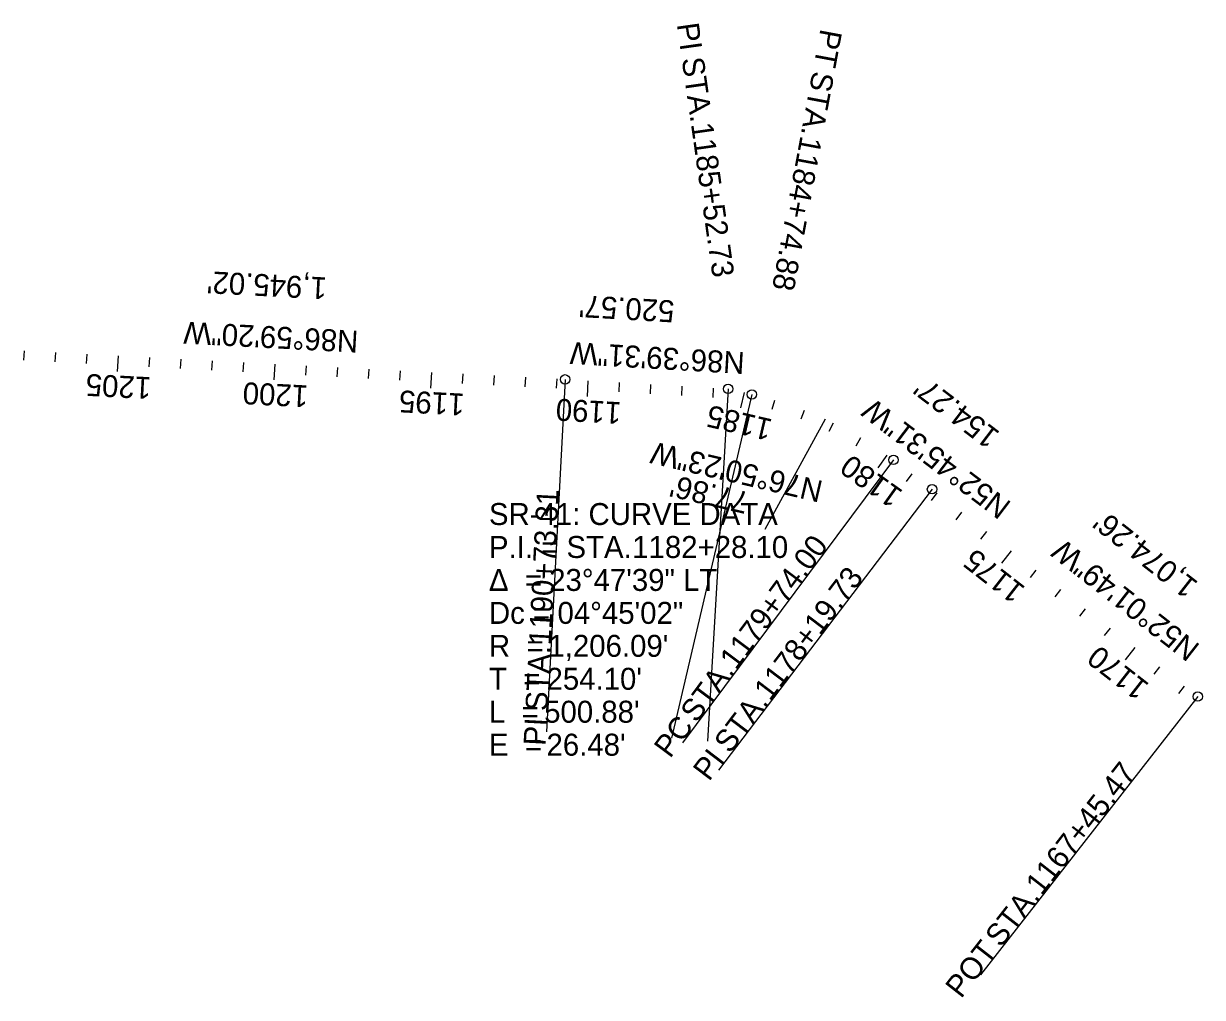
# Model space of a CAD drawing. Extents: x 99589 to 110840, y 526591 to 533644.
# Drawn here: x 107082 to 110840, y 526591 to 529695 of the extents above; entities that cross this region are included whole.
import ezdxf

# ---------------------------------------------------------------- set-up
doc = ezdxf.new("R2010")
doc.units = 0
for name, color, linetype in [('GE_P_Alignment_500_Bearings', 7, 'Continuous'), ('GE_P_Alignment_500_Cardinal_Points', 7, 'Continuous'), ('GE_P_Alignment_500_Curve_Data', 7, 'Continuous'), ('GE_P_Alignment_500_Distances', 7, 'Continuous'), ('GE_P_Alignment_500_Stations', 7, 'Continuous')]:
    doc.layers.add(name, color=color, linetype=linetype)

msp = doc.modelspace()

# ---------------------------------------------------------------- linework, layer by layer
at = {"layer": 'GE_P_Alignment_500_Cardinal_Points'}
for p, q in [((108808.4, 528561), (108749.3, 527437.6)), ((109328, 528530.7), (109262.5, 527407.6)), ((109403.9, 528513), (109147.7, 527417.5)), ((109855.3, 528304.4), (109183, 527402.3)), ((109978.1, 528211), (109297.3, 527315.4)), ((110825, 527550.1), (110132.8, 526663.2))]:
    msp.add_line(p, q, dxfattribs=at)
for centre in [(108808.4, 528561), (109328, 528530.7), (109403.9, 528513), (109855.3, 528304.4), (109978.1, 528211), (110825, 527550.1)]:
    msp.add_circle(centre, 15, dxfattribs=at)
at = {"layer": 'GE_P_Alignment_500_Curve_Data'}
msp.add_line((109637.1, 528433.7), (109445.2, 528082.6), dxfattribs=at)
at = {"layer": 'GE_P_Alignment_500_Stations'}
for p, q in [((107084, 528651.7), (107082.5, 528621.8)), ((107183.9, 528646.5), (107182.3, 528616.5)), ((107283.8, 528641.2), (107282.2, 528611.3)), ((107383.6, 528636), (107381, 528586)), ((107483.5, 528630.7), (107481.9, 528600.8)), ((107583.4, 528625.5), (107581.8, 528595.5)), ((107683.2, 528620.2), (107681.6, 528590.3)), ((107783.1, 528615), (107781.5, 528585)), ((107882.9, 528609.7), (107880.3, 528559.8)), ((107982.8, 528604.5), (107981.2, 528574.5)), ((108082.7, 528599.2), (108081.1, 528569.2)), ((108182.5, 528593.9), (108180.9, 528564)), ((108282.4, 528588.7), (108280.8, 528558.7)), ((108382.2, 528583.4), (108379.6, 528533.5)), ((108482.1, 528578.2), (108480.5, 528548.2)), ((108582, 528572.9), (108580.4, 528543)), ((108681.8, 528567.7), (108680.3, 528537.7)), ((108781.7, 528562.4), (108780.1, 528532.5)), ((108881.5, 528556.8), (108878.6, 528506.8)), ((108981.4, 528550.9), (108979.6, 528521)), ((109081.2, 528545.1), (109079.4, 528515.1)), ((109181, 528539.3), (109179.3, 528509.3)), ((109280.9, 528533.4), (109279.1, 528503.5)), ((109379.4, 528518.7), (109368, 528470)), ((109476.3, 528494), (109467.8, 528465.2)), ((109570.9, 528461.7), (109560, 528433.7)), ((109662.5, 528421.7), (109649.4, 528394.7)), ((109750.5, 528374.3), (109735.2, 528348.5)), ((109834.3, 528319.7), (109805.3, 528279)), ((109914.2, 528259.6), (109896, 528235.7)), ((109993.6, 528198.9), (109975.2, 528175.2)), ((110072.5, 528137.4), (110054, 528113.7)), ((110151.3, 528075.8), (110132.9, 528052.2)), ((110230.1, 528014.3), (110199.4, 527974.9)), ((110309, 527952.8), (110290.5, 527929.1)), ((110387.8, 527891.3), (110369.4, 527867.6)), ((110466.7, 527829.7), (110448.2, 527806.1)), ((110545.5, 527768.2), (110527, 527744.6)), ((110624.3, 527706.7), (110593.6, 527667.3)), ((110703.2, 527645.2), (110684.7, 527621.5)), ((110782, 527583.6), (110763.5, 527560))]:
    msp.add_line(p, q, dxfattribs=at)

# ---------------------------------------------------------------- texts
at = {"layer": 'GE_P_Alignment_500_Bearings'}
for s, rotation, p in [('N86°59\'20"W', 176.989, (108150.9, 528715.8)), ('N86°39\'31"W', 176.6585, (109382.5, 528647.7)), ('N52°45\'31"W', 142.7585, (110234.4, 528166.9)), ('N76°50\'23"W', 166.8397, (109634.2, 528236.2)), ('N52°01\'49"W', 142.0302, (110835.7, 527713))]:
    msp.add_text(s, height=70, rotation=rotation, dxfattribs=at).set_placement(p)
at = {"layer": 'GE_P_Alignment_500_Cardinal_Points'}
for s, rotation, p in [('PI', 278.0637, (109164.5, 529692.6)), ('PT', 259.42, (109623, 529680.4)), (' STA. ', 278.0637, (109176.4, 529608.7)), (' STA. ', 259.42, (109602.7, 529571.9)), ('1185+52.73', 278.0637, (109209.5, 529374.7)), ('1184+74.88', 259.42, (109559.3, 529339.6)), ('1190+73.31', 86.989, (108762.7, 527712.9)), ('1179+74.00', 53.3042, (109352.9, 527632.1)), ('1178+19.73', 52.7585, (109461.4, 527533.1)), (' STA. ', 86.989, (108750.3, 527477)), (' STA. ', 53.3042, (109211.7, 527442.6)), (' STA. ', 52.7585, (109318.4, 527345)), ('PC', 53.3042, (109143.2, 527350.7)), ('PI', 86.989, (108745.8, 527392.3)), ('PI', 52.7585, (109267.1, 527277.5)), ('1167+45.47', 52.0302, (110326.8, 526913.5)), (' STA. ', 52.0302, (110181.4, 526727.2)), ('POT', 52.0302, (110070.7, 526585.3))]:
    msp.add_text(s, height=70, rotation=rotation, dxfattribs=at).set_placement(p)
at = {"layer": 'GE_P_Alignment_500_Curve_Data'}
for s, p in [('SR-41: CURVE DATA', (108565.8, 528096.8)), ('P.I. = STA. ', (108565.8, 527991.8)), ('1182+28.10', (109022.5, 527991.8)), ('Δ  = ', (108565.8, 527886.8)), ('23°47\'39" LT', (108757.8, 527886.8)), ('Dc = ', (108565.8, 527781.8)), ('04°45\'02"', (108784.3, 527781.8)), ('R  = ', (108565.8, 527676.8)), ("1,206.09'", (108755.4, 527676.8)), ('T  = ', (108565.8, 527571.8)), ("254.10'", (108749.3, 527571.8)), ('L  = ', (108565.8, 527466.8)), ("500.88'", (108741.8, 527466.8)), ('E  = ', (108565.8, 527361.8)), ("26.48'", (108749.3, 527361.8))]:
    msp.add_text(s, height=70, dxfattribs=at).set_placement(p)
at = {"layer": 'GE_P_Alignment_500_Distances'}
for s, rotation, p in [("1,945.02'", 176.989, (108050.7, 528885.6)), ("520.57'", 176.6585, (109158.7, 528812)), ("154.27'", 142.7585, (110197.8, 528391.2)), ("77.86'", 166.8397, (109398.7, 528199.9)), ("1,074.26'", 142.0302, (110829.8, 527913))]:
    msp.add_text(s, height=70, rotation=rotation, dxfattribs=at).set_placement(p)
at = {"layer": 'GE_P_Alignment_500_Stations'}
for s, rotation, p in [('1205', 176.989, (107490.7, 528567.7)), ('1200', 176.989, (107991.1, 528541.4)), ('1195', 176.989, (108489.4, 528515.2)), ('1190', 176.6585, (108989.3, 528487.9)), ('1185', 166.8397, (109472.8, 528432.6)), ('1180', 144.5393, (109888.9, 528204)), ('1175', 142.0302, (110278.9, 527897)), ('1170', 142.0302, (110673.8, 527588.7))]:
    msp.add_text(s, height=70, rotation=rotation, dxfattribs=at).set_placement(p)

doc.saveas('drawing.dxf')
